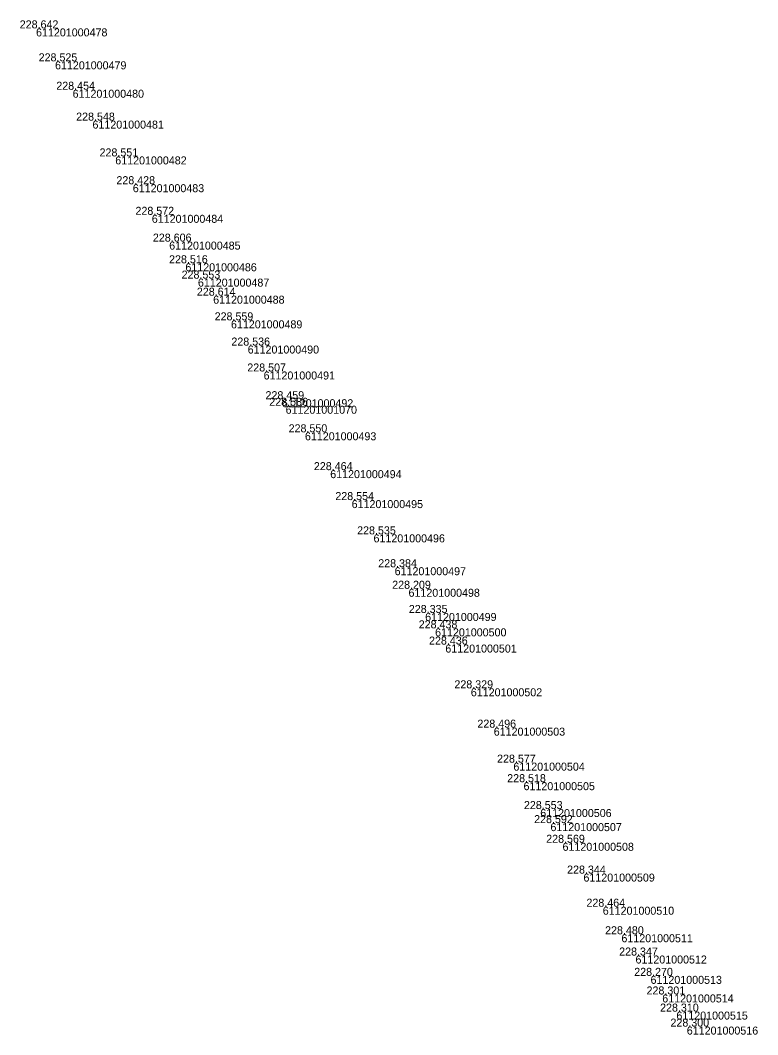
# Model space of a CAD drawing. Extents: x -771040 to -768909, y -1052366 to -1050115.
# Drawn here: x -769459.8 to -769349.1, y -1050673.2 to -1050521.1 of the extents above; entities that cross this region are included whole.
import ezdxf

# ---------------------------------------------------------------- set-up
doc = ezdxf.new("R2010")
doc.units = 0
doc.layers.add('Vrstva 60', color=7, linetype='Continuous')
doc.layers.add('Vrstva 61', color=7, linetype='Continuous')

msp = doc.modelspace()

# ---------------------------------------------------------------- linework, layer by layer
at = {"layer": 'Vrstva 60'}
for p, q in [((-769457.42, -1050522.27), (-769457.42, -1050522.27)), ((-769454.57, -1050527.21), (-769454.57, -1050527.21)), ((-769451.93, -1050531.47), (-769451.93, -1050531.47)), ((-769448.95, -1050536.1), (-769448.95, -1050536.1)), ((-769445.53, -1050541.47), (-769445.53, -1050541.47)), ((-769442.9, -1050545.64), (-769442.9, -1050545.64)), ((-769440.05, -1050550.23), (-769440.05, -1050550.23)), ((-769437.44, -1050554.25), (-769437.44, -1050554.25)), ((-769435.01, -1050557.5), (-769435.01, -1050557.5)), ((-769433.13, -1050559.8), (-769433.13, -1050559.8)), ((-769430.84, -1050562.36), (-769430.84, -1050562.36)), ((-769428.17, -1050566.06), (-769428.17, -1050566.06)), ((-769425.66, -1050569.84), (-769425.66, -1050569.84)), ((-769423.27, -1050573.73), (-769423.27, -1050573.73)), ((-769420.53, -1050577.89), (-769420.53, -1050577.89)), ((-769419.97, -1050578.87), (-769419.97, -1050578.87)), ((-769417.07, -1050582.85), (-769417.07, -1050582.85)), ((-769413.28, -1050588.53), (-769413.28, -1050588.53)), ((-769410.06, -1050593.02), (-769410.06, -1050593.02)), ((-769406.78, -1050598.16), (-769406.78, -1050598.16)), ((-769403.61, -1050603.09), (-769403.61, -1050603.09)), ((-769401.53, -1050606.32), (-769401.53, -1050606.32)), ((-769399.03, -1050609.95), (-769399.03, -1050609.95)), ((-769397.54, -1050612.26), (-769397.54, -1050612.26)), ((-769396, -1050614.69), (-769396, -1050614.69)), ((-769392.18, -1050621.25), (-769392.18, -1050621.25)), ((-769388.74, -1050627.15), (-769388.74, -1050627.15)), ((-769385.79, -1050632.4), (-769385.79, -1050632.4)), ((-769384.27, -1050635.33), (-769384.27, -1050635.33)), ((-769381.76, -1050639.36), (-769381.76, -1050639.36)), ((-769380.23, -1050641.47), (-769380.23, -1050641.47)), ((-769378.42, -1050644.42), (-769378.42, -1050644.42)), ((-769375.28, -1050649.04), (-769375.28, -1050649.04)), ((-769372.38, -1050654.01), (-769372.38, -1050654.01)), ((-769369.58, -1050658.14), (-769369.58, -1050658.14)), ((-769367.47, -1050661.33), (-769367.47, -1050661.33)), ((-769365.21, -1050664.38), (-769365.21, -1050664.38)), ((-769363.45, -1050667.17), (-769363.45, -1050667.17)), ((-769361.33, -1050669.74), (-769361.33, -1050669.74)), ((-769359.77, -1050671.99), (-769359.77, -1050671.99))]:
    msp.add_line(p, q, dxfattribs=at)

# ---------------------------------------------------------------- texts
for s, p in [('611201000478', (-769457.42, -1050523.47)), ('611201000479', (-769454.57, -1050528.41)), ('611201000480', (-769451.93, -1050532.67)), ('611201000481', (-769448.95, -1050537.3)), ('611201000482', (-769445.53, -1050542.67)), ('611201000483', (-769442.9, -1050546.84)), ('611201000484', (-769440.05, -1050551.43)), ('611201000485', (-769437.44, -1050555.45)), ('611201000486', (-769435.01, -1050558.7)), ('611201000487', (-769433.13, -1050561)), ('611201000488', (-769430.84, -1050563.56)), ('611201000489', (-769428.17, -1050567.26)), ('611201000490', (-769425.66, -1050571.04)), ('611201000491', (-769423.27, -1050574.93)), ('611201000492', (-769420.53, -1050579.09)), ('611201001070', (-769419.97, -1050580.07)), ('611201000493', (-769417.07, -1050584.05)), ('611201000494', (-769413.28, -1050589.73)), ('611201000495', (-769410.06, -1050594.22)), ('611201000496', (-769406.78, -1050599.36)), ('611201000497', (-769403.61, -1050604.29)), ('611201000498', (-769401.53, -1050607.52)), ('611201000499', (-769399.03, -1050611.15)), ('611201000500', (-769397.54, -1050613.46)), ('611201000501', (-769396, -1050615.89)), ('611201000502', (-769392.18, -1050622.45)), ('611201000503', (-769388.74, -1050628.35)), ('611201000504', (-769385.79, -1050633.6)), ('611201000505', (-769384.27, -1050636.53)), ('611201000506', (-769381.76, -1050640.56)), ('611201000507', (-769380.23, -1050642.67)), ('611201000508', (-769378.42, -1050645.62)), ('611201000509', (-769375.28, -1050650.24)), ('611201000510', (-769372.38, -1050655.21)), ('611201000511', (-769369.58, -1050659.34)), ('611201000512', (-769367.47, -1050662.53)), ('611201000513', (-769365.21, -1050665.58)), ('611201000514', (-769363.45, -1050668.37)), ('611201000515', (-769361.33, -1050670.94)), ('611201000516', (-769359.77, -1050673.19))]:
    msp.add_text(s, height=1.2, dxfattribs=at).set_placement(p)
at = {"layer": 'Vrstva 61'}
for s, p in [('228.642', (-769459.87, -1050522.27)), ('228.525', (-769457.03, -1050527.21)), ('228.454', (-769454.38, -1050531.47)), ('228.548', (-769451.4, -1050536.1)), ('228.551', (-769447.89, -1050541.47)), ('228.428', (-769445.36, -1050545.64)), ('228.572', (-769442.5, -1050550.23)), ('228.606', (-769439.89, -1050554.25)), ('228.516', (-769437.46, -1050557.5)), ('228.553', (-769435.58, -1050559.8)), ('228.614', (-769433.29, -1050562.36)), ('228.559', (-769430.62, -1050566.06)), ('228.536', (-769428.11, -1050569.84)), ('228.507', (-769425.72, -1050573.73)), ('228.459', (-769422.99, -1050577.89)), ('228.586', (-769422.42, -1050578.87)), ('228.550', (-769419.52, -1050582.85)), ('228.464', (-769415.73, -1050588.53)), ('228.554', (-769412.51, -1050593.02)), ('228.535', (-769409.24, -1050598.16)), ('228.384', (-769406.07, -1050603.09)), ('228.209', (-769403.98, -1050606.32)), ('228.335', (-769401.48, -1050609.95)), ('228.438', (-769400, -1050612.26)), ('228.436', (-769398.45, -1050614.69)), ('228.329', (-769394.64, -1050621.25)), ('228.496', (-769391.19, -1050627.15)), ('228.577', (-769388.24, -1050632.4)), ('228.518', (-769386.72, -1050635.33)), ('228.553', (-769384.21, -1050639.36)), ('228.592', (-769382.68, -1050641.47)), ('228.569', (-769380.87, -1050644.42)), ('228.344', (-769377.73, -1050649.04)), ('228.464', (-769374.83, -1050654.01)), ('228.480', (-769372.03, -1050658.14)), ('228.347', (-769369.92, -1050661.33)), ('228.270', (-769367.66, -1050664.38)), ('228.301', (-769365.81, -1050667.17)), ('228.310', (-769363.78, -1050669.74)), ('228.300', (-769362.22, -1050671.99))]:
    msp.add_text(s, height=1.2, dxfattribs=at).set_placement(p)

doc.saveas('drawing.dxf')
